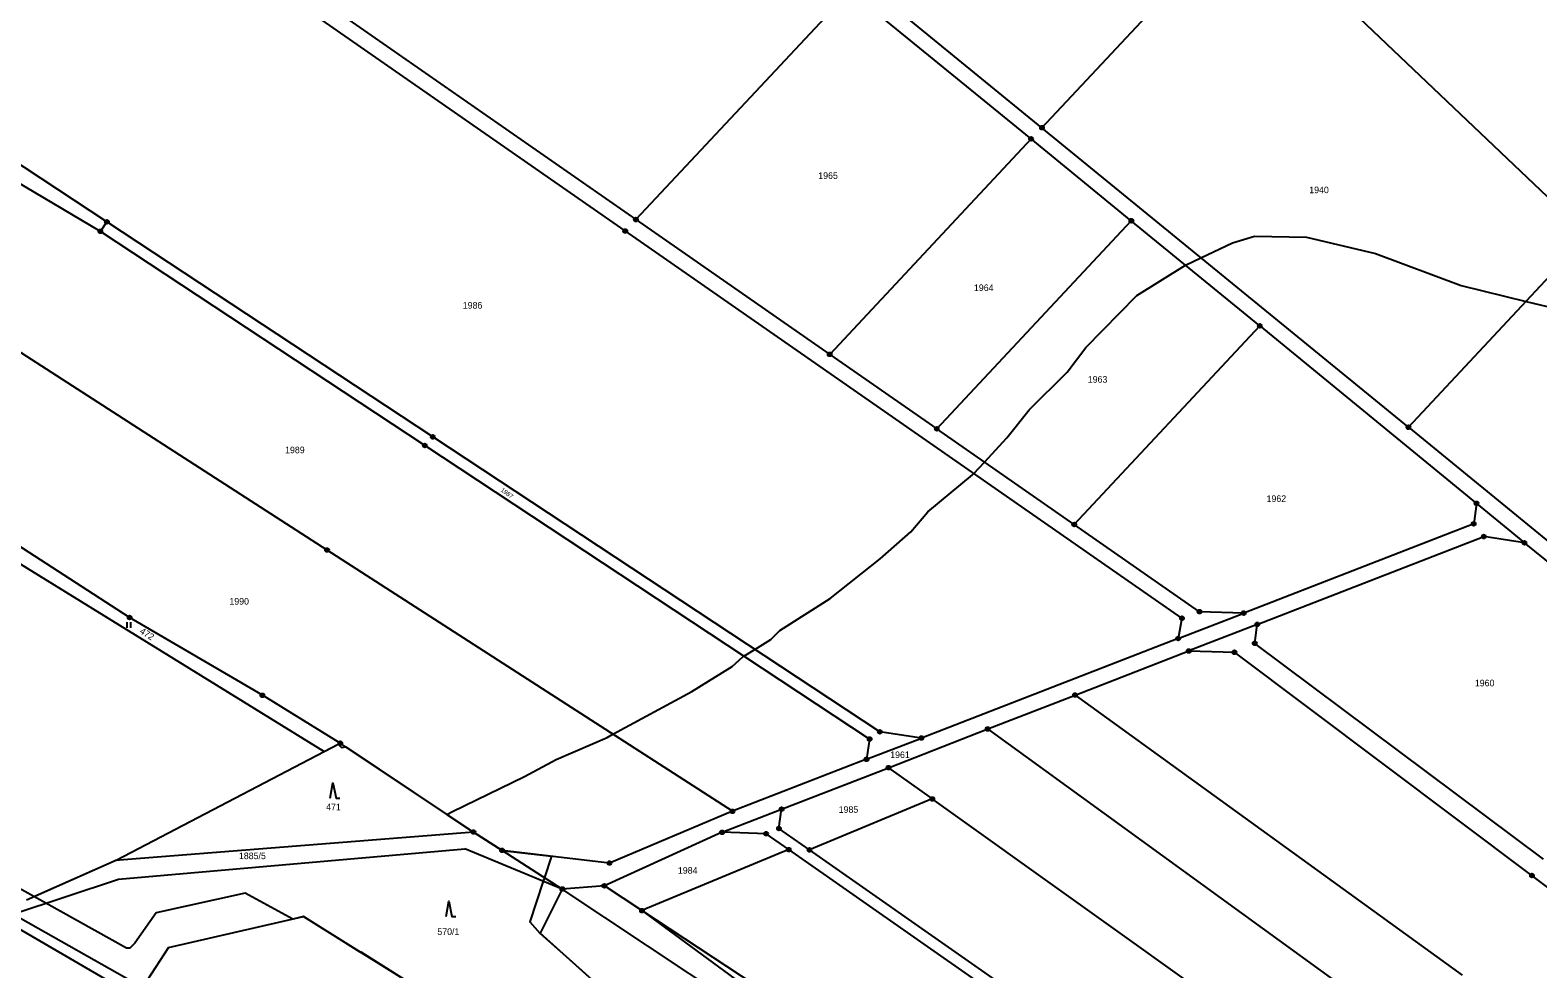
# Model space of a CAD drawing. Extents: x -445050 to -440454, y -1134563 to -1129741.
# Drawn here: x -442582.2 to -442192.6, y -1131669.9 to -1131427.4 of the extents above; entities that cross this region are included whole.
import ezdxf

# ---------------------------------------------------------------- set-up
doc = ezdxf.new("R2010")
doc.units = 0
for name, color, linetype in [('Vrstva 1', 7, 'Continuous'), ('Vrstva 18', 7, 'Continuous'), ('Vrstva 24', 7, 'Continuous'), ('Vrstva 25', 7, 'Continuous'), ('Vrstva 52', 7, 'Continuous')]:
    doc.layers.add(name, color=color, linetype=linetype)

msp = doc.modelspace()

# ---------------------------------------------------------------- linework, layer by layer
at = {"layer": 'Vrstva 1'}
msp.add_line((-442502.92, -1131422.6), (-442425.66, -1131476.33), dxfattribs=at)
for points in [[(-442428.42, -1131479.28), (-442598.39, -1131361.08)], [(-442320.74, -1131452.6), (-442268.09, -1131396.29)], [(-442179.67, -1131480.38), (-442268.09, -1131396.29)], [(-442320.74, -1131452.6), (-442370.14, -1131412.24)], [(-442370.38, -1131417.2), (-442425.66, -1131476.33)], [(-442323.54, -1131455.47), (-442370.38, -1131417.2)], [(-442562.37, -1131476.91), (-442630.31, -1131432.09)], [(-442564.05, -1131479.38), (-442634.59, -1131437.65)], [(-442226.04, -1131529.98), (-442320.74, -1131452.6)], [(-442323.54, -1131455.47), (-442375.59, -1131511.15)], [(-442297.64, -1131476.64), (-442323.54, -1131455.47)], [(-442505.47, -1131561.71), (-442655.64, -1131464.97)], [(-442564.05, -1131479.38), (-442562.37, -1131476.91)], [(-442478.15, -1131532.48), (-442562.37, -1131476.91)], [(-442425.66, -1131476.33), (-442375.59, -1131511.15)], [(-442347.9, -1131530.4), (-442297.64, -1131476.64)], [(-442264.42, -1131503.79), (-442297.64, -1131476.64)], [(-442480.22, -1131534.7), (-442564.05, -1131479.38)], [(-442284.56, -1131579.33), (-442428.42, -1131479.28)], [(-442226.04, -1131529.98), (-442179.67, -1131480.38)], [(-442312.39, -1131555.1), (-442264.42, -1131503.79)], [(-442264.42, -1131503.79), (-442208.44, -1131549.64)], [(-442375.59, -1131511.15), (-442347.9, -1131530.4)], [(-442362.64, -1131608.68), (-442478.15, -1131532.48)], [(-442312.39, -1131555.1), (-442347.9, -1131530.4)], [(-442226.04, -1131529.98), (-442153.16, -1131589.53)], [(-442556.5, -1131579.12), (-442622.41, -1131536.5)], [(-442365.27, -1131610.54), (-442480.22, -1131534.7)], [(-442208.44, -1131549.64), (-442209.17, -1131554.94)], [(-442208.44, -1131549.64), (-442196.04, -1131559.85)], [(-442280.02, -1131577.63), (-442312.39, -1131555.1)], [(-442209.17, -1131554.94), (-442268.6, -1131577.99)], [(-442594.09, -1131559.59), (-442506.26, -1131613.79)], [(-442265.09, -1131580.92), (-442206.56, -1131558.22)], [(-442196.04, -1131559.85), (-442206.56, -1131558.22)], [(-442149.7, -1131597.19), (-442196.04, -1131559.85)], [(-442400.7, -1131629.2), (-442505.47, -1131561.71)], [(-442522.19, -1131599.24), (-442556.5, -1131579.12)], [(-442285.53, -1131584.55), (-442268.6, -1131577.99)], [(-442284.56, -1131579.33), (-442285.53, -1131584.55)], [(-442268.6, -1131577.99), (-442280.02, -1131577.63)], [(-442265.09, -1131580.92), (-442282.81, -1131587.78)], [(-442265.74, -1131585.81), (-442265.09, -1131580.92)], [(-442285.53, -1131584.55), (-442351.89, -1131610.27)], [(-442191.15, -1131641.54), (-442265.74, -1131585.81)], [(-442312.18, -1131599.17), (-442282.81, -1131587.78)], [(-442282.81, -1131587.78), (-442271, -1131588.11)], [(-442194.11, -1131645.78), (-442271, -1131588.11)], [(-442502.06, -1131611.6), (-442522.19, -1131599.24)], [(-442334.76, -1131607.93), (-442312.18, -1131599.17)], [(-442312.18, -1131599.17), (-442212.12, -1131671.53)], [(-442366.05, -1131615.77), (-442351.89, -1131610.27)], [(-442365.27, -1131610.54), (-442366.05, -1131615.77)], [(-442351.89, -1131610.27), (-442362.64, -1131608.68)], [(-442360.38, -1131617.93), (-442334.76, -1131607.93)], [(-442223.84, -1131688.29), (-442334.76, -1131607.93)], [(-442559.94, -1131641.82), (-442506.26, -1131613.79)], [(-442506.26, -1131613.79), (-442502.06, -1131611.6)], [(-442467.65, -1131634.56), (-442502.06, -1131611.6)], [(-442366.05, -1131615.77), (-442400.7, -1131629.2)], [(-442388, -1131628.65), (-442360.38, -1131617.93)], [(-442360.38, -1131617.93), (-442349.07, -1131626.01)], [(-442349.07, -1131626.01), (-442380.81, -1131639.17)], [(-442236.51, -1131706.4), (-442349.07, -1131626.01)], [(-442400.7, -1131629.2), (-442432.48, -1131642.57)], [(-442403.4, -1131634.63), (-442388, -1131628.65)], [(-442388.7, -1131633.65), (-442388, -1131628.65)], [(-442380.81, -1131639.17), (-442388.7, -1131633.65)], [(-442467.65, -1131634.56), (-442560.23, -1131641.95)], [(-442460.25, -1131639.3), (-442467.65, -1131634.56)], [(-442403.4, -1131634.63), (-442433.82, -1131648.46)], [(-442392.02, -1131634.99), (-442403.4, -1131634.63)], [(-442386.14, -1131639.11), (-442392.02, -1131634.99)], [(-442559.37, -1131646.74), (-442469.89, -1131638.92)], [(-442444.68, -1131649.28), (-442469.89, -1131638.92)], [(-442444.68, -1131649.28), (-442460.25, -1131639.3)], [(-442432.48, -1131642.57), (-442460.25, -1131639.3)], [(-442386.14, -1131639.11), (-442424.1, -1131654.87)], [(-442254.05, -1131731.48), (-442386.14, -1131639.11)], [(-442252.34, -1131729.03), (-442380.81, -1131639.17)], [(-442583.14, -1131652.06), (-442560.23, -1131641.95)], [(-442560.23, -1131641.95), (-442559.94, -1131641.82)], [(-442586.64, -1131655.78), (-442559.37, -1131646.74)], [(-442444.68, -1131649.28), (-442450.38, -1131660.67)], [(-442433.82, -1131648.46), (-442444.68, -1131649.28)], [(-442346, -1131714.89), (-442444.68, -1131649.28)], [(-442424.1, -1131654.87), (-442433.82, -1131648.46)], [(-442053.64, -1131751.13), (-442194.11, -1131645.78)], [(-442553.17, -1131674.75), (-442586.64, -1131655.78)], [(-442546.41, -1131664.41), (-442511.57, -1131656.39)], [(-442511.57, -1131656.39), (-442462.31, -1131687.15)], [(-442424.1, -1131654.87), (-442376.08, -1131690.14)], [(-442365.3, -1131693.62), (-442424.1, -1131654.87)], [(-442506.53, -1131705.31), (-442588.49, -1131657.59)], [(-442399.48, -1131706.41), (-442450.38, -1131660.67)], [(-442546.41, -1131664.41), (-442553.17, -1131674.75)]]:
    msp.add_lwpolyline(points, dxfattribs=at)
at = {"layer": 'Vrstva 24'}
for centre, radius in [((-442320.74, -1131452.6), 0.5), ((-442320.74, -1131452.6), 0.1), ((-442323.54, -1131455.47), 0.5), ((-442323.54, -1131455.47), 0.1), ((-442562.37, -1131476.91), 0.5), ((-442562.37, -1131476.91), 0.1), ((-442425.66, -1131476.33), 0.5), ((-442425.66, -1131476.33), 0.1), ((-442297.64, -1131476.64), 0.5), ((-442297.64, -1131476.64), 0.1), ((-442564.05, -1131479.38), 0.5), ((-442564.05, -1131479.38), 0.1), ((-442428.42, -1131479.28), 0.5), ((-442428.42, -1131479.28), 0.1), ((-442264.42, -1131503.79), 0.5), ((-442264.42, -1131503.79), 0.1), ((-442375.59, -1131511.15), 0.5), ((-442375.59, -1131511.15), 0.1), ((-442478.15, -1131532.48), 0.5), ((-442478.15, -1131532.48), 0.1), ((-442347.9, -1131530.4), 0.5), ((-442347.9, -1131530.4), 0.1), ((-442226.04, -1131529.98), 0.5), ((-442226.04, -1131529.98), 0.1), ((-442480.22, -1131534.7), 0.5), ((-442480.22, -1131534.7), 0.1), ((-442208.44, -1131549.64), 0.5), ((-442208.44, -1131549.64), 0.1), ((-442312.39, -1131555.1), 0.5), ((-442312.39, -1131555.1), 0.1), ((-442209.17, -1131554.94), 0.5), ((-442209.17, -1131554.94), 0.1), ((-442206.56, -1131558.22), 0.5), ((-442206.56, -1131558.22), 0.1), ((-442196.04, -1131559.85), 0.5), ((-442196.04, -1131559.85), 0.1), ((-442505.47, -1131561.71), 0.5), ((-442505.47, -1131561.71), 0.1), ((-442556.5, -1131579.12), 0.5), ((-442556.5, -1131579.12), 0.1), ((-442284.56, -1131579.33), 0.5), ((-442284.56, -1131579.33), 0.1), ((-442280.02, -1131577.63), 0.5), ((-442280.02, -1131577.63), 0.1), ((-442268.6, -1131577.99), 0.5), ((-442268.6, -1131577.99), 0.1), ((-442265.09, -1131580.92), 0.5), ((-442265.09, -1131580.92), 0.1), ((-442285.53, -1131584.55), 0.5), ((-442285.53, -1131584.55), 0.1), ((-442265.74, -1131585.81), 0.5), ((-442265.74, -1131585.81), 0.1), ((-442282.81, -1131587.78), 0.5), ((-442282.81, -1131587.78), 0.1), ((-442271, -1131588.11), 0.5), ((-442271, -1131588.11), 0.1), ((-442522.19, -1131599.24), 0.5), ((-442312.18, -1131599.17), 0.5), ((-442522.19, -1131599.24), 0.1), ((-442312.18, -1131599.17), 0.1), ((-442365.27, -1131610.54), 0.5), ((-442365.27, -1131610.54), 0.1), ((-442362.64, -1131608.68), 0.5), ((-442362.64, -1131608.68), 0.1), ((-442351.89, -1131610.27), 0.5), ((-442351.89, -1131610.27), 0.1), ((-442334.76, -1131607.93), 0.5), ((-442334.76, -1131607.93), 0.1), ((-442502.06, -1131611.6), 0.5), ((-442502.06, -1131611.6), 0.1), ((-442366.05, -1131615.77), 0.5), ((-442366.05, -1131615.77), 0.1), ((-442360.38, -1131617.93), 0.5), ((-442360.38, -1131617.93), 0.1), ((-442349.07, -1131626.01), 0.5), ((-442349.07, -1131626.01), 0.1), ((-442400.7, -1131629.2), 0.5), ((-442400.7, -1131629.2), 0.1), ((-442388, -1131628.65), 0.5), ((-442388, -1131628.65), 0.1), ((-442388.7, -1131633.65), 0.5), ((-442388.7, -1131633.65), 0.1), ((-442467.65, -1131634.56), 0.5), ((-442467.65, -1131634.56), 0.1), ((-442403.4, -1131634.63), 0.5), ((-442403.4, -1131634.63), 0.1), ((-442392.02, -1131634.99), 0.5), ((-442392.02, -1131634.99), 0.1), ((-442460.25, -1131639.3), 0.5), ((-442460.25, -1131639.3), 0.1), ((-442386.14, -1131639.11), 0.5), ((-442386.14, -1131639.11), 0.1), ((-442380.81, -1131639.17), 0.5), ((-442380.81, -1131639.17), 0.1), ((-442432.48, -1131642.57), 0.5), ((-442432.48, -1131642.57), 0.1), ((-442194.11, -1131645.78), 0.5), ((-442444.68, -1131649.28), 0.5), ((-442444.68, -1131649.28), 0.1), ((-442433.82, -1131648.46), 0.5), ((-442433.82, -1131648.46), 0.1), ((-442194.11, -1131645.78), 0.1), ((-442424.1, -1131654.87), 0.5), ((-442424.1, -1131654.87), 0.1)]:
    msp.add_circle(centre, radius, dxfattribs=at)
at = {"layer": 'Vrstva 25'}
for p, q in [((-442557.16, -1131581.83), (-442557.16, -1131580.33)), ((-442556.16, -1131581.83), (-442556.16, -1131580.33))]:
    msp.add_line(p, q, dxfattribs=at)
for points in [[(-442504.65, -1131625.83), (-442503.95, -1131621.83), (-442503.15, -1131625.83), (-442502.15, -1131625.83)], [(-442474.7, -1131656.41), (-442474, -1131652.41), (-442473.2, -1131656.41), (-442472.2, -1131656.41)]]:
    msp.add_lwpolyline(points, dxfattribs=at)
at = {"layer": 'Vrstva 52'}
for points in [[(-442474.49, -1131630), (-442473.06, -1131629.26), (-442454.42, -1131620.23), (-442446.28, -1131615.86), (-442433.1, -1131610.12), (-442431.6, -1131609.3), (-442411.2, -1131598.21), (-442400.79, -1131591.83), (-442398.02, -1131589.28), (-442397.75, -1131589.11), (-442394.94, -1131587.38), (-442390.8, -1131584.82), (-442388.46, -1131582.48), (-442375.49, -1131574.19), (-442362.52, -1131563.98), (-442354.65, -1131556.97), (-442350.19, -1131551.86), (-442338.71, -1131542.3), (-442338.35, -1131541.92), (-442335.59, -1131538.96), (-442329.78, -1131532.73), (-442324.04, -1131525.5), (-442314.26, -1131515.72), (-442309.37, -1131509.35), (-442296.19, -1131495.95), (-442283.65, -1131488.09), (-442279.64, -1131486.19), (-442271.53, -1131482.35), (-442265.79, -1131480.65), (-442252.4, -1131480.86), (-442234.54, -1131485.11), (-442212.43, -1131493.4), (-442195.64, -1131497.46), (-442186.92, -1131499.57)], [(-442581.26, -1131651.23), (-442560.23, -1131641.95), (-442559.94, -1131641.82), (-442506.26, -1131613.79), (-442502.6, -1131611.88), (-442501.78, -1131612.69), (-442500.61, -1131612.57), (-442474.49, -1131630)], [(-442474.49, -1131630), (-442467.65, -1131634.56), (-442460.25, -1131639.3), (-442447.44, -1131640.81), (-442449.28, -1131646.33), (-442449.59, -1131647.26), (-442453.09, -1131657.74), (-442450.53, -1131660.71), (-442443.02, -1131667.28), (-442417.69, -1131690.04)], [(-442581.26, -1131651.23), (-442600.88, -1131640.34), (-442626.15, -1131632.27)], [(-442417.69, -1131690.04), (-442401.23, -1131704.84), (-442401, -1131705.36), (-442404.55, -1131727.83), (-442461.25, -1131695.88), (-442462.31, -1131687.15), (-442484.25, -1131673.45), (-442496.67, -1131665.6), (-442496.9, -1131665.55), (-442511.57, -1131656.39), (-442514.35, -1131657.03), (-442526.66, -1131650.31), (-442549.62, -1131655.41), (-442555.14, -1131663.28), (-442556.42, -1131664.56), (-442557.27, -1131664.56), (-442578.14, -1131652.96), (-442581.26, -1131651.23)]]:
    msp.add_lwpolyline(points, dxfattribs=at)

# ---------------------------------------------------------------- texts
at = {"layer": 'Vrstva 18'}
for s, p in [('1965', (-442378.54, -1131465.82)), ('1940', (-442251.66, -1131469.51)), ('1964', (-442338.31, -1131494.79)), ('1986', (-442470.4, -1131499.33)), ('1963', (-442308.89, -1131518.47)), ('1989', (-442516.32, -1131536.69)), ('1962', (-442262.69, -1131549.28)), ('1990', (-442530.71, -1131575.81)), ('1960', (-442208.87, -1131596.91)), ('1961', (-442359.95, -1131615.45)), ('471', (-442505.71, -1131628.93)), ('1985', (-442373.26, -1131629.6)), ('1885/5', (-442528.25, -1131641.56)), ('1984', (-442414.81, -1131645.33)), ('570/1', (-442476.98, -1131661.14))]:
    msp.add_text(s, height=1.7, dxfattribs=at).set_placement(p)
for s, height, rotation, p in [('1987', 1.14, 323.6334, (-442460.71, -1131546.41)), ('472', 1.7, 327.2292, (-442554.05, -1131583.07))]:
    msp.add_text(s, height=height, rotation=rotation, dxfattribs=at).set_placement(p)

doc.saveas('drawing.dxf')
